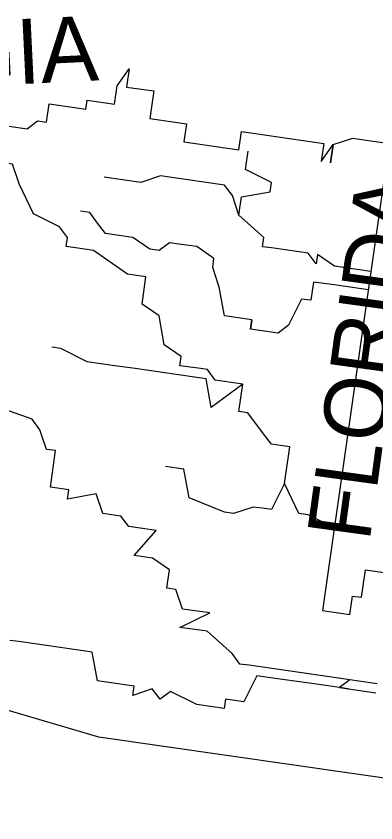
# Model space of a CAD drawing. Extents: x 1797205 to 1798536, y 248101 to 249940.
# Drawn here: x 1798376.79 to 1798387.01, y 249014.57 to 249037.48 of the extents above; entities that cross this region are included whole.
import ezdxf

# ---------------------------------------------------------------- set-up
doc = ezdxf.new("R2010")
doc.units = 0
doc.layers.add('great seal', color=7, linetype='Continuous')

msp = doc.modelspace()

# ---------------------------------------------------------------- linework, layer by layer
at = {"layer": 'great seal'}
for points in [[(1798376.58, 249034.356), (1798377.1, 249034.282), (1798377.397, 249034.504), (1798377.657, 249034.467), (1798377.657, 249034.467), (1798377.732, 249034.987), (1798378.512, 249034.875), (1798378.772, 249034.838), (1798378.809, 249035.098), (1798379.07, 249035.061), (1798379.07, 249035.061), (1798379.33, 249035.024), (1798379.59, 249034.986), (1798379.664, 249035.507), (1798379.999, 249035.99), (1798379.924, 249035.469), (1798380.705, 249035.358), (1798380.705, 249035.358), (1798380.63, 249034.837), (1798380.63, 249034.837), (1798380.63, 249034.837), (1798380.63, 249034.837), (1798380.593, 249034.577), (1798380.593, 249034.577), (1798380.593, 249034.577), (1798380.853, 249034.54), (1798381.113, 249034.503), (1798381.113, 249034.503), (1798381.113, 249034.503), (1798381.113, 249034.503), (1798381.113, 249034.503), (1798381.373, 249034.465), (1798381.373, 249034.465), (1798381.373, 249034.465), (1798381.633, 249034.428), (1798381.633, 249034.428), (1798381.559, 249033.908), (1798381.559, 249033.908), (1798381.559, 249033.908), (1798381.819, 249033.871), (1798381.819, 249033.871), (1798382.339, 249033.796), (1798382.339, 249033.796), (1798382.339, 249033.796), (1798382.339, 249033.796), (1798382.339, 249033.796), (1798382.339, 249033.796), (1798382.339, 249033.796), (1798382.859, 249033.722), (1798382.859, 249033.722), (1798382.859, 249033.722), (1798382.859, 249033.722), (1798382.859, 249033.722), (1798382.859, 249033.722), (1798383.119, 249033.684), (1798383.194, 249034.204), (1798383.454, 249034.167), (1798383.454, 249034.167), (1798383.454, 249034.167), (1798384.234, 249034.055), (1798384.234, 249034.055), (1798384.234, 249034.055), (1798384.234, 249034.055), (1798384.234, 249034.055), (1798384.234, 249034.055), (1798384.495, 249034.018), (1798385.015, 249033.944), (1798385.015, 249033.944), (1798385.015, 249033.944), (1798385.275, 249033.906), (1798385.275, 249033.906), (1798385.535, 249033.869), (1798385.535, 249033.869), (1798385.46, 249033.349), (1798385.46, 249033.349), (1798385.46, 249033.349), (1798385.46, 249033.349), (1798385.795, 249033.832), (1798385.795, 249033.832), (1798385.721, 249033.311), (1798385.795, 249033.832), (1798385.795, 249033.832), (1798385.795, 249033.832), (1798386.353, 249034.017), (1798386.353, 249034.017), (1798386.613, 249033.98), (1798386.613, 249033.98), (1798387.393, 249033.868), (1798385.492, 249020.603), (1798385.752, 249020.565), (1798385.752, 249020.565)], [(1798376.58, 249034.356), (1798377.1, 249034.282), (1798377.397, 249034.504), (1798377.657, 249034.467), (1798377.657, 249034.467), (1798377.732, 249034.987), (1798378.512, 249034.875), (1798378.772, 249034.838), (1798378.809, 249035.098), (1798379.07, 249035.061), (1798379.07, 249035.061), (1798379.33, 249035.024), (1798379.59, 249034.986), (1798379.664, 249035.507), (1798379.999, 249035.99), (1798379.924, 249035.469), (1798380.705, 249035.358), (1798380.705, 249035.358), (1798380.63, 249034.837), (1798380.63, 249034.837), (1798380.63, 249034.837), (1798380.63, 249034.837), (1798380.593, 249034.577), (1798380.593, 249034.577), (1798380.593, 249034.577), (1798380.853, 249034.54), (1798381.113, 249034.503), (1798381.113, 249034.503), (1798381.113, 249034.503), (1798381.113, 249034.503), (1798381.113, 249034.503), (1798381.373, 249034.465), (1798381.373, 249034.465), (1798381.373, 249034.465), (1798381.633, 249034.428), (1798381.633, 249034.428), (1798381.559, 249033.908), (1798381.559, 249033.908), (1798381.559, 249033.908), (1798381.819, 249033.871), (1798381.819, 249033.871), (1798382.339, 249033.796), (1798382.339, 249033.796), (1798382.339, 249033.796), (1798382.339, 249033.796), (1798382.339, 249033.796), (1798382.339, 249033.796), (1798382.339, 249033.796), (1798382.859, 249033.722), (1798382.859, 249033.722), (1798382.859, 249033.722), (1798382.859, 249033.722), (1798382.859, 249033.722), (1798382.859, 249033.722), (1798383.119, 249033.684), (1798383.194, 249034.204), (1798383.454, 249034.167), (1798383.454, 249034.167), (1798383.454, 249034.167), (1798384.234, 249034.055), (1798384.234, 249034.055), (1798384.234, 249034.055), (1798384.234, 249034.055), (1798384.234, 249034.055), (1798384.234, 249034.055), (1798384.495, 249034.018), (1798385.015, 249033.944), (1798385.015, 249033.944), (1798385.015, 249033.944), (1798385.275, 249033.906), (1798385.275, 249033.906), (1798385.535, 249033.869), (1798385.535, 249033.869), (1798385.46, 249033.349), (1798385.46, 249033.349), (1798385.46, 249033.349), (1798385.46, 249033.349), (1798385.795, 249033.832), (1798385.795, 249033.832), (1798385.721, 249033.311), (1798385.795, 249033.832), (1798385.795, 249033.832), (1798385.795, 249033.832), (1798386.353, 249034.017), (1798386.353, 249034.017), (1798386.613, 249033.98), (1798386.613, 249033.98), (1798387.393, 249033.868), (1798385.492, 249020.603), (1798385.752, 249020.565), (1798385.752, 249020.565)], [(1798376.58, 249034.356), (1798377.1, 249034.282), (1798377.397, 249034.504), (1798377.657, 249034.467), (1798377.657, 249034.467), (1798377.732, 249034.987), (1798378.512, 249034.875), (1798378.772, 249034.838), (1798378.809, 249035.098), (1798379.07, 249035.061), (1798379.07, 249035.061), (1798379.33, 249035.024), (1798379.59, 249034.986), (1798379.664, 249035.507), (1798379.999, 249035.99), (1798379.924, 249035.469), (1798380.705, 249035.358), (1798380.705, 249035.358), (1798380.63, 249034.837), (1798380.63, 249034.837), (1798380.63, 249034.837), (1798380.63, 249034.837), (1798380.593, 249034.577), (1798380.593, 249034.577), (1798380.593, 249034.577), (1798380.853, 249034.54), (1798381.113, 249034.503), (1798381.113, 249034.503), (1798381.113, 249034.503), (1798381.113, 249034.503), (1798381.113, 249034.503), (1798381.373, 249034.465), (1798381.373, 249034.465), (1798381.373, 249034.465), (1798381.633, 249034.428), (1798381.633, 249034.428), (1798381.559, 249033.908), (1798381.559, 249033.908), (1798381.559, 249033.908), (1798381.819, 249033.871), (1798381.819, 249033.871), (1798382.339, 249033.796), (1798382.339, 249033.796), (1798382.339, 249033.796), (1798382.339, 249033.796), (1798382.339, 249033.796), (1798382.339, 249033.796), (1798382.339, 249033.796), (1798382.859, 249033.722), (1798382.859, 249033.722), (1798382.859, 249033.722), (1798382.859, 249033.722), (1798382.859, 249033.722), (1798382.859, 249033.722), (1798383.119, 249033.684), (1798383.194, 249034.204), (1798383.454, 249034.167), (1798383.454, 249034.167), (1798383.454, 249034.167), (1798384.234, 249034.055), (1798384.234, 249034.055), (1798384.234, 249034.055), (1798384.234, 249034.055), (1798384.234, 249034.055), (1798384.234, 249034.055), (1798384.495, 249034.018), (1798385.015, 249033.944), (1798385.015, 249033.944), (1798385.015, 249033.944), (1798385.275, 249033.906), (1798385.275, 249033.906), (1798385.535, 249033.869), (1798385.535, 249033.869), (1798385.46, 249033.349), (1798385.46, 249033.349), (1798385.46, 249033.349), (1798385.46, 249033.349), (1798385.795, 249033.832), (1798385.795, 249033.832), (1798385.721, 249033.311), (1798385.795, 249033.832), (1798385.795, 249033.832), (1798385.795, 249033.832), (1798386.353, 249034.017), (1798386.353, 249034.017), (1798386.613, 249033.98), (1798386.613, 249033.98), (1798387.393, 249033.868), (1798385.492, 249020.603), (1798385.752, 249020.565), (1798385.752, 249020.565)], [(1798386.871, 249030.227), (1798386.091, 249030.338), (1798386.091, 249030.338), (1798385.831, 249030.376), (1798385.348, 249030.71), (1798385.31, 249030.45), (1798385.088, 249030.748), (1798384.828, 249030.785), (1798384.567, 249030.822), (1798384.567, 249030.822), (1798384.047, 249030.897), (1798383.787, 249030.934), (1798383.824, 249031.194), (1798383.119, 249031.826), (1798383.193, 249032.346), (1798384.011, 249032.495), (1798384.048, 249032.755), (1798383.305, 249033.127), (1798383.342, 249033.387), (1798383.38, 249033.647)], [(1798386.871, 249030.227), (1798386.091, 249030.338), (1798386.091, 249030.338), (1798385.831, 249030.376), (1798385.348, 249030.71), (1798385.31, 249030.45), (1798385.088, 249030.748), (1798384.828, 249030.785), (1798384.567, 249030.822), (1798384.567, 249030.822), (1798384.047, 249030.897), (1798383.787, 249030.934), (1798383.824, 249031.194), (1798383.119, 249031.826), (1798383.193, 249032.346), (1798384.011, 249032.495), (1798384.048, 249032.755), (1798383.305, 249033.127), (1798383.342, 249033.387), (1798383.38, 249033.647)], [(1798386.871, 249030.227), (1798386.091, 249030.338), (1798386.091, 249030.338), (1798385.831, 249030.376), (1798385.348, 249030.71), (1798385.31, 249030.45), (1798385.088, 249030.748), (1798384.828, 249030.785), (1798384.567, 249030.822), (1798384.567, 249030.822), (1798384.047, 249030.897), (1798383.787, 249030.934), (1798383.824, 249031.194), (1798383.119, 249031.826), (1798383.193, 249032.346), (1798384.011, 249032.495), (1798384.048, 249032.755), (1798383.305, 249033.127), (1798383.342, 249033.387), (1798383.38, 249033.647)], [(1798383.228, 249027.032), (1798383.228, 249027.032), (1798382.448, 249027.144), (1798382.225, 249027.442), (1798381.965, 249027.479), (1798381.444, 249027.554), (1798381.482, 249027.814), (1798380.999, 249028.148), (1798380.851, 249028.966), (1798380.368, 249029.301), (1798380.479, 249030.081), (1798379.959, 249030.155), (1798378.993, 249030.825), (1798378.473, 249030.899), (1798378.473, 249030.899), (1798378.213, 249030.937), (1798378.25, 249031.197), (1798378.027, 249031.494), (1798377.284, 249031.866), (1798376.876, 249032.721), (1798376.691, 249033.278), (1798376.43, 249033.316), (1798376.17, 249033.353), (1798376.096, 249032.833)], [(1798383.228, 249027.032), (1798383.228, 249027.032), (1798382.448, 249027.144), (1798382.225, 249027.442), (1798381.965, 249027.479), (1798381.444, 249027.554), (1798381.482, 249027.814), (1798380.999, 249028.148), (1798380.851, 249028.966), (1798380.368, 249029.301), (1798380.479, 249030.081), (1798379.959, 249030.155), (1798378.993, 249030.825), (1798378.473, 249030.899), (1798378.473, 249030.899), (1798378.213, 249030.937), (1798378.25, 249031.197), (1798378.027, 249031.494), (1798377.284, 249031.866), (1798376.876, 249032.721), (1798376.691, 249033.278), (1798376.43, 249033.316), (1798376.17, 249033.353), (1798376.096, 249032.833)], [(1798383.228, 249027.032), (1798383.228, 249027.032), (1798382.448, 249027.144), (1798382.225, 249027.442), (1798381.965, 249027.479), (1798381.444, 249027.554), (1798381.482, 249027.814), (1798380.999, 249028.148), (1798380.851, 249028.966), (1798380.368, 249029.301), (1798380.479, 249030.081), (1798379.959, 249030.155), (1798378.993, 249030.825), (1798378.473, 249030.899), (1798378.473, 249030.899), (1798378.213, 249030.937), (1798378.25, 249031.197), (1798378.027, 249031.494), (1798377.284, 249031.866), (1798376.876, 249032.721), (1798376.691, 249033.278), (1798376.43, 249033.316), (1798376.17, 249033.353), (1798376.096, 249032.833)], [(1798383.119, 249031.826), (1798383.119, 249031.826), (1798382.933, 249032.384), (1798382.71, 249032.681), (1798382.71, 249032.681), (1798382.19, 249032.756), (1798381.67, 249032.83), (1798381.41, 249032.867), (1798381.15, 249032.905), (1798380.889, 249032.942), (1798380.332, 249032.756), (1798380.332, 249032.756), (1798379.292, 249032.906)], [(1798383.119, 249031.826), (1798383.119, 249031.826), (1798382.933, 249032.384), (1798382.71, 249032.681), (1798382.71, 249032.681), (1798382.19, 249032.756), (1798381.67, 249032.83), (1798381.41, 249032.867), (1798381.15, 249032.905), (1798380.889, 249032.942), (1798380.332, 249032.756), (1798380.332, 249032.756), (1798379.292, 249032.906)], [(1798383.119, 249031.826), (1798383.119, 249031.826), (1798382.933, 249032.384), (1798382.71, 249032.681), (1798382.71, 249032.681), (1798382.19, 249032.756), (1798381.67, 249032.83), (1798381.41, 249032.867), (1798381.15, 249032.905), (1798380.889, 249032.942), (1798380.332, 249032.756), (1798380.332, 249032.756), (1798379.292, 249032.906)], [(1798386.797, 249029.706), (1798386.016, 249029.818), (1798385.756, 249029.856), (1798385.236, 249029.93), (1798385.236, 249029.93), (1798385.161, 249029.41), (1798384.901, 249029.447), (1798384.529, 249028.704), (1798384.232, 249028.481), (1798383.712, 249028.556), (1798383.452, 249028.593), (1798383.489, 249028.853), (1798383.452, 249028.593), (1798383.489, 249028.853), (1798382.709, 249028.965), (1798382.56, 249029.783), (1798382.375, 249030.34), (1798382.375, 249030.34), (1798382.412, 249030.6), (1798381.929, 249030.935), (1798381.929, 249030.935), (1798381.409, 249031.009), (1798381.149, 249031.047), (1798381.149, 249031.047), (1798380.851, 249030.824), (1798380.591, 249030.861), (1798380.108, 249031.196), (1798379.328, 249031.308), (1798379.105, 249031.605), (1798378.882, 249031.902), (1798378.622, 249031.94)], [(1798386.797, 249029.706), (1798386.016, 249029.818), (1798385.756, 249029.856), (1798385.236, 249029.93), (1798385.236, 249029.93), (1798385.161, 249029.41), (1798384.901, 249029.447), (1798384.529, 249028.704), (1798384.232, 249028.481), (1798383.712, 249028.556), (1798383.452, 249028.593), (1798383.489, 249028.853), (1798383.452, 249028.593), (1798383.489, 249028.853), (1798382.709, 249028.965), (1798382.56, 249029.783), (1798382.375, 249030.34), (1798382.375, 249030.34), (1798382.412, 249030.6), (1798381.929, 249030.935), (1798381.929, 249030.935), (1798381.409, 249031.009), (1798381.149, 249031.047), (1798381.149, 249031.047), (1798380.851, 249030.824), (1798380.591, 249030.861), (1798380.108, 249031.196), (1798379.328, 249031.308), (1798379.105, 249031.605), (1798378.882, 249031.902), (1798378.622, 249031.94)], [(1798386.797, 249029.706), (1798386.016, 249029.818), (1798385.756, 249029.856), (1798385.236, 249029.93), (1798385.236, 249029.93), (1798385.161, 249029.41), (1798384.901, 249029.447), (1798384.529, 249028.704), (1798384.232, 249028.481), (1798383.712, 249028.556), (1798383.452, 249028.593), (1798383.489, 249028.853), (1798383.452, 249028.593), (1798383.489, 249028.853), (1798382.709, 249028.965), (1798382.56, 249029.783), (1798382.375, 249030.34), (1798382.375, 249030.34), (1798382.412, 249030.6), (1798381.929, 249030.935), (1798381.929, 249030.935), (1798381.409, 249031.009), (1798381.149, 249031.047), (1798381.149, 249031.047), (1798380.851, 249030.824), (1798380.591, 249030.861), (1798380.108, 249031.196), (1798379.328, 249031.308), (1798379.105, 249031.605), (1798378.882, 249031.902), (1798378.622, 249031.94)], [(1798384.416, 249024.208), (1798384.416, 249024.208), (1798384.49, 249024.728), (1798384.528, 249024.988), (1798384.565, 249025.248), (1798384.305, 249025.285), (1798384.045, 249025.323), (1798383.822, 249025.62), (1798383.376, 249026.215), (1798383.116, 249026.252), (1798383.228, 249027.032), (1798383.228, 249027.032), (1798382.336, 249026.364), (1798382.187, 249027.182), (1798381.927, 249027.219), (1798381.407, 249027.293), (1798380.887, 249027.368), (1798380.627, 249027.405), (1798380.107, 249027.48), (1798380.107, 249027.48), (1798379.586, 249027.554), (1798378.806, 249027.666), (1798378.063, 249028.038), (1798378.063, 249028.038), (1798377.803, 249028.075)], [(1798384.416, 249024.208), (1798384.416, 249024.208), (1798384.49, 249024.728), (1798384.528, 249024.988), (1798384.565, 249025.248), (1798384.305, 249025.285), (1798384.045, 249025.323), (1798383.822, 249025.62), (1798383.376, 249026.215), (1798383.116, 249026.252), (1798383.228, 249027.032), (1798383.228, 249027.032), (1798382.336, 249026.364), (1798382.187, 249027.182), (1798381.927, 249027.219), (1798381.407, 249027.293), (1798380.887, 249027.368), (1798380.627, 249027.405), (1798380.107, 249027.48), (1798380.107, 249027.48), (1798379.586, 249027.554), (1798378.806, 249027.666), (1798378.063, 249028.038), (1798378.063, 249028.038), (1798377.803, 249028.075)], [(1798384.416, 249024.208), (1798384.416, 249024.208), (1798384.49, 249024.728), (1798384.528, 249024.988), (1798384.565, 249025.248), (1798384.305, 249025.285), (1798384.045, 249025.323), (1798383.822, 249025.62), (1798383.376, 249026.215), (1798383.116, 249026.252), (1798383.228, 249027.032), (1798383.228, 249027.032), (1798382.336, 249026.364), (1798382.187, 249027.182), (1798381.927, 249027.219), (1798381.407, 249027.293), (1798380.887, 249027.368), (1798380.627, 249027.405), (1798380.107, 249027.48), (1798380.107, 249027.48), (1798379.586, 249027.554), (1798378.806, 249027.666), (1798378.063, 249028.038), (1798378.063, 249028.038), (1798377.803, 249028.075)], [(1798386.271, 249018.633), (1798386.011, 249018.67), (1798385.491, 249018.745), (1798385.491, 249018.745), (1798384.451, 249018.894), (1798384.19, 249018.931), (1798383.67, 249019.006), (1798383.67, 249019.006), (1798383.41, 249019.043), (1798383.15, 249019.08), (1798382.927, 249019.378), (1798382.221, 249020.01), (1798381.441, 249020.121), (1798382.296, 249020.53), (1798381.516, 249020.642), (1798381.33, 249021.199), (1798381.07, 249021.236), (1798381.145, 249021.757), (1798380.662, 249022.091), (1798380.141, 249022.166), (1798380.773, 249022.872), (1798379.993, 249022.983), (1798379.77, 249023.281), (1798379.51, 249023.318), (1798379.25, 249023.355), (1798379.065, 249023.913), (1798378.247, 249023.765), (1798378.284, 249024.025), (1798377.764, 249024.099), (1798377.913, 249025.14), (1798377.653, 249025.177), (1798377.653, 249025.177), (1798377.467, 249025.734), (1798377.245, 249026.032), (1798375.981, 249026.478)], [(1798386.271, 249018.633), (1798386.011, 249018.67), (1798385.491, 249018.745), (1798385.491, 249018.745), (1798384.451, 249018.894), (1798384.19, 249018.931), (1798383.67, 249019.006), (1798383.67, 249019.006), (1798383.41, 249019.043), (1798383.15, 249019.08), (1798382.927, 249019.378), (1798382.221, 249020.01), (1798381.441, 249020.121), (1798382.296, 249020.53), (1798381.516, 249020.642), (1798381.33, 249021.199), (1798381.07, 249021.236), (1798381.145, 249021.757), (1798380.662, 249022.091), (1798380.141, 249022.166), (1798380.773, 249022.872), (1798379.993, 249022.983), (1798379.77, 249023.281), (1798379.51, 249023.318), (1798379.25, 249023.355), (1798379.065, 249023.913), (1798378.247, 249023.765), (1798378.284, 249024.025), (1798377.764, 249024.099), (1798377.913, 249025.14), (1798377.653, 249025.177), (1798377.653, 249025.177), (1798377.467, 249025.734), (1798377.245, 249026.032), (1798375.981, 249026.478)], [(1798386.271, 249018.633), (1798386.011, 249018.67), (1798385.491, 249018.745), (1798385.491, 249018.745), (1798384.451, 249018.894), (1798384.19, 249018.931), (1798383.67, 249019.006), (1798383.67, 249019.006), (1798383.41, 249019.043), (1798383.15, 249019.08), (1798382.927, 249019.378), (1798382.221, 249020.01), (1798381.441, 249020.121), (1798382.296, 249020.53), (1798381.516, 249020.642), (1798381.33, 249021.199), (1798381.07, 249021.236), (1798381.145, 249021.757), (1798380.662, 249022.091), (1798380.141, 249022.166), (1798380.773, 249022.872), (1798379.993, 249022.983), (1798379.77, 249023.281), (1798379.51, 249023.318), (1798379.25, 249023.355), (1798379.065, 249023.913), (1798378.247, 249023.765), (1798378.284, 249024.025), (1798377.764, 249024.099), (1798377.913, 249025.14), (1798377.653, 249025.177), (1798377.653, 249025.177), (1798377.467, 249025.734), (1798377.245, 249026.032), (1798375.981, 249026.478)], [(1798385.827, 249022.944), (1798385.084, 249023.316), (1798384.824, 249023.353), (1798384.416, 249024.208), (1798384.416, 249024.208), (1798384.416, 249024.208), (1798384.044, 249023.465), (1798383.784, 249023.502), (1798383.524, 249023.539), (1798382.966, 249023.354), (1798382.706, 249023.391), (1798382.706, 249023.391), (1798381.703, 249023.8), (1798381.555, 249024.618), (1798381.034, 249024.692)], [(1798385.827, 249022.944), (1798385.084, 249023.316), (1798384.824, 249023.353), (1798384.416, 249024.208), (1798384.416, 249024.208), (1798384.416, 249024.208), (1798384.044, 249023.465), (1798383.784, 249023.502), (1798383.524, 249023.539), (1798382.966, 249023.354), (1798382.706, 249023.391), (1798382.706, 249023.391), (1798381.703, 249023.8), (1798381.555, 249024.618), (1798381.034, 249024.692)], [(1798385.827, 249022.944), (1798385.084, 249023.316), (1798384.824, 249023.353), (1798384.416, 249024.208), (1798384.416, 249024.208), (1798384.416, 249024.208), (1798384.044, 249023.465), (1798383.784, 249023.502), (1798383.524, 249023.539), (1798382.966, 249023.354), (1798382.706, 249023.391), (1798382.706, 249023.391), (1798381.703, 249023.8), (1798381.555, 249024.618), (1798381.034, 249024.692)], [(1798388.239, 249015.696), (1798379.136, 249017.001), (1798363.345, 249021.653)], [(1798388.239, 249015.696), (1798379.136, 249017.001), (1798363.345, 249021.653)], [(1798388.239, 249015.696), (1798379.136, 249017.001), (1798363.345, 249021.653)], [(1798385.752, 249020.565), (1798386.012, 249020.528), (1798386.012, 249020.528), (1798386.272, 249020.491), (1798386.272, 249020.491), (1798386.347, 249021.011), (1798386.347, 249021.011), (1798386.607, 249020.974), (1798386.644, 249021.234), (1798386.644, 249021.234), (1798386.644, 249021.234), (1798386.719, 249021.754), (1798386.719, 249021.754), (1798386.719, 249021.754), (1798386.979, 249021.717), (1798386.979, 249021.717), (1798386.979, 249021.717), (1798387.499, 249021.642)], [(1798385.752, 249020.565), (1798386.012, 249020.528), (1798386.012, 249020.528), (1798386.272, 249020.491), (1798386.272, 249020.491), (1798386.347, 249021.011), (1798386.347, 249021.011), (1798386.607, 249020.974), (1798386.644, 249021.234), (1798386.644, 249021.234), (1798386.644, 249021.234), (1798386.719, 249021.754), (1798386.719, 249021.754), (1798386.719, 249021.754), (1798386.979, 249021.717), (1798386.979, 249021.717), (1798386.979, 249021.717), (1798387.499, 249021.642)], [(1798385.752, 249020.565), (1798386.012, 249020.528), (1798386.012, 249020.528), (1798386.272, 249020.491), (1798386.272, 249020.491), (1798386.347, 249021.011), (1798386.347, 249021.011), (1798386.607, 249020.974), (1798386.644, 249021.234), (1798386.644, 249021.234), (1798386.644, 249021.234), (1798386.719, 249021.754), (1798386.719, 249021.754), (1798386.719, 249021.754), (1798386.979, 249021.717), (1798386.979, 249021.717), (1798386.979, 249021.717), (1798387.499, 249021.642)], [(1798386.234, 249018.373), (1798385.974, 249018.41), (1798385.454, 249018.485), (1798385.454, 249018.485), (1798385.194, 249018.522), (1798385.194, 249018.522), (1798384.153, 249018.671), (1798383.633, 249018.746), (1798383.633, 249018.746), (1798383.261, 249018.002), (1798383.001, 249018.04), (1798382.741, 249018.077), (1798382.703, 249017.817), (1798381.923, 249017.929), (1798381.923, 249017.929), (1798381.18, 249018.301), (1798380.883, 249018.078), (1798380.66, 249018.375), (1798380.102, 249018.19), (1798380.102, 249018.19), (1798380.102, 249018.19), (1798380.14, 249018.45), (1798379.359, 249018.562), (1798379.359, 249018.562), (1798379.099, 249018.599), (1798378.951, 249019.417), (1798378.691, 249019.454), (1798378.431, 249019.491), (1798377.65, 249019.603), (1798377.39, 249019.64), (1798376.87, 249019.715), (1798376.87, 249019.715), (1798376.61, 249019.752)], [(1798386.234, 249018.373), (1798385.974, 249018.41), (1798385.454, 249018.485), (1798385.454, 249018.485), (1798385.194, 249018.522), (1798385.194, 249018.522), (1798384.153, 249018.671), (1798383.633, 249018.746), (1798383.633, 249018.746), (1798383.261, 249018.002), (1798383.001, 249018.04), (1798382.741, 249018.077), (1798382.703, 249017.817), (1798381.923, 249017.929), (1798381.923, 249017.929), (1798381.18, 249018.301), (1798380.883, 249018.078), (1798380.66, 249018.375), (1798380.102, 249018.19), (1798380.102, 249018.19), (1798380.102, 249018.19), (1798380.14, 249018.45), (1798379.359, 249018.562), (1798379.359, 249018.562), (1798379.099, 249018.599), (1798378.951, 249019.417), (1798378.691, 249019.454), (1798378.431, 249019.491), (1798377.65, 249019.603), (1798377.39, 249019.64), (1798376.87, 249019.715), (1798376.87, 249019.715), (1798376.61, 249019.752)], [(1798386.234, 249018.373), (1798385.974, 249018.41), (1798385.454, 249018.485), (1798385.454, 249018.485), (1798385.194, 249018.522), (1798385.194, 249018.522), (1798384.153, 249018.671), (1798383.633, 249018.746), (1798383.633, 249018.746), (1798383.261, 249018.002), (1798383.001, 249018.04), (1798382.741, 249018.077), (1798382.703, 249017.817), (1798381.923, 249017.929), (1798381.923, 249017.929), (1798381.18, 249018.301), (1798380.883, 249018.078), (1798380.66, 249018.375), (1798380.102, 249018.19), (1798380.102, 249018.19), (1798380.102, 249018.19), (1798380.14, 249018.45), (1798379.359, 249018.562), (1798379.359, 249018.562), (1798379.099, 249018.599), (1798378.951, 249019.417), (1798378.691, 249019.454), (1798378.431, 249019.491), (1798377.65, 249019.603), (1798377.39, 249019.64), (1798376.87, 249019.715), (1798376.87, 249019.715), (1798376.61, 249019.752)], [(1798387.052, 249018.521), (1798386.531, 249018.596), (1798386.531, 249018.596), (1798386.271, 249018.633), (1798386.271, 249018.633), (1798386.271, 249018.633), (1798386.271, 249018.633), (1798386.271, 249018.633), (1798386.271, 249018.633), (1798386.271, 249018.633), (1798385.974, 249018.41)], [(1798387.052, 249018.521), (1798386.531, 249018.596), (1798386.531, 249018.596), (1798386.271, 249018.633), (1798386.271, 249018.633), (1798386.271, 249018.633), (1798386.271, 249018.633), (1798386.271, 249018.633), (1798386.271, 249018.633), (1798386.271, 249018.633), (1798385.974, 249018.41)], [(1798387.052, 249018.521), (1798386.531, 249018.596), (1798386.531, 249018.596), (1798386.271, 249018.633), (1798386.271, 249018.633), (1798386.271, 249018.633), (1798386.271, 249018.633), (1798386.271, 249018.633), (1798386.271, 249018.633), (1798386.271, 249018.633), (1798385.974, 249018.41)], [(1798385.974, 249018.41), (1798385.974, 249018.41), (1798386.234, 249018.373), (1798386.234, 249018.373), (1798386.234, 249018.373), (1798386.234, 249018.373), (1798386.234, 249018.373), (1798386.234, 249018.373), (1798386.494, 249018.335), (1798387.014, 249018.261)], [(1798385.974, 249018.41), (1798385.974, 249018.41), (1798386.234, 249018.373), (1798386.234, 249018.373), (1798386.234, 249018.373), (1798386.234, 249018.373), (1798386.234, 249018.373), (1798386.234, 249018.373), (1798386.494, 249018.335), (1798387.014, 249018.261)], [(1798385.974, 249018.41), (1798385.974, 249018.41), (1798386.234, 249018.373), (1798386.234, 249018.373), (1798386.234, 249018.373), (1798386.234, 249018.373), (1798386.234, 249018.373), (1798386.234, 249018.373), (1798386.494, 249018.335), (1798387.014, 249018.261)], [(1798386.271, 249018.633), (1798386.271, 249018.633)], [(1798386.271, 249018.633), (1798386.271, 249018.633)], [(1798386.271, 249018.633), (1798386.271, 249018.633)]]:
    msp.add_lwpolyline(points, dxfattribs=at)
for radius in [22.994, 22.994, 22.994, 22.389, 22.389, 22.389, 17.779, 17.779, 17.779, 17.222, 17.222, 17.222]:
    msp.add_circle((1798376.426, 249026.432), radius, dxfattribs=at)

# ---------------------------------------------------------------- texts
for s, height, rotation, p in [('GEORGIA', 1.8446, 2.7735, (1798367.661, 249035.103)), ('GEORGIA', 1.8446, 2.7735, (1798367.661, 249035.103)), ('GEORGIA', 1.8446, 2.7735, (1798367.661, 249035.103)), ('FLORIDA', 1.7942, 82.1677, (1798386.83, 249022.534)), ('FLORIDA', 1.7942, 82.1677, (1798386.83, 249022.534)), ('FLORIDA', 1.7942, 82.1677, (1798386.83, 249022.534)), ('N', 5.851, 32.4862, (1798387.939, 249008.041)), ('N', 5.851, 32.4862, (1798387.939, 249008.041)), ('N', 5.851, 32.4862, (1798387.939, 249008.041))]:
    msp.add_text(s, height=height, rotation=rotation, dxfattribs=at).set_placement(p)

doc.saveas('drawing.dxf')
